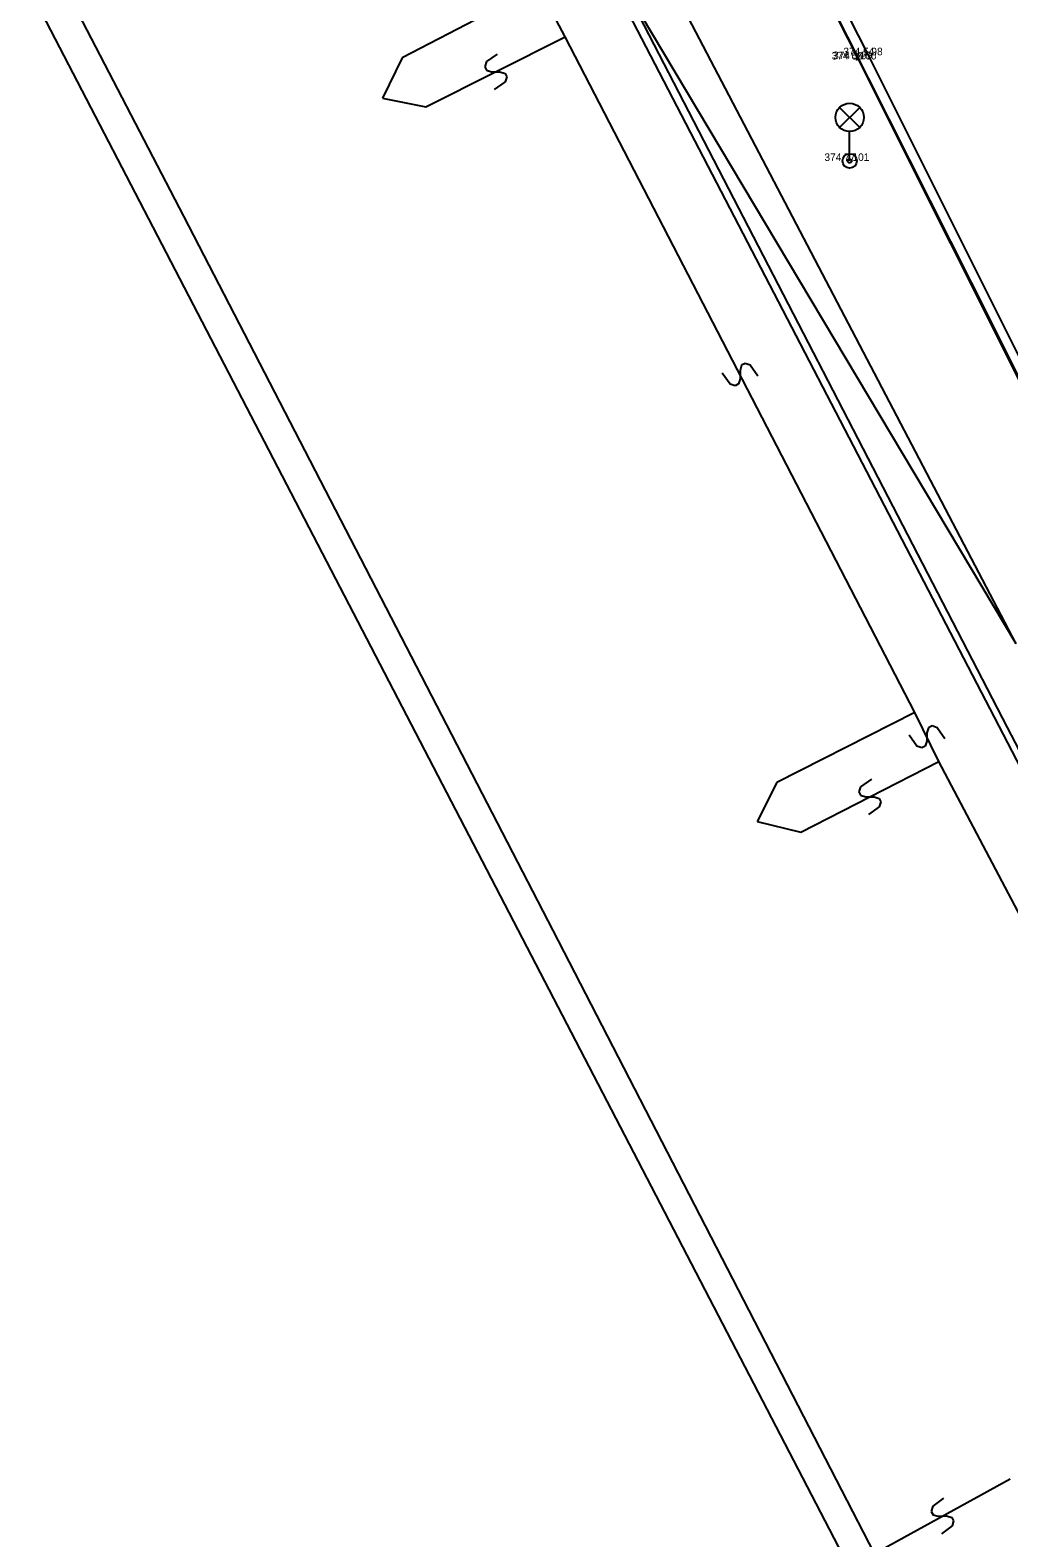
# Model space of a CAD drawing. Extents: x -601196 to -600262, y -1082523 to -1081922.
# Drawn here: x -600494.1 to -600468.24, y -1082356.61 to -1082316.78 of the extents above; entities that cross this region are included whole.
import ezdxf

# ---------------------------------------------------------------- set-up
doc = ezdxf.new("R2010")
doc.units = 0
for name, color, linetype in [('Vrstva 1', 7, 'Continuous'), ('Vrstva 10', 7, 'Continuous'), ('Vrstva 11', 7, 'Continuous'), ('Vrstva 2', 7, 'Continuous'), ('Vrstva 20', 7, 'Continuous'), ('Vrstva 3', 7, 'Continuous'), ('Vrstva 33', 7, 'Continuous'), ('Vrstva 47', 7, 'Continuous')]:
    doc.layers.add(name, color=color, linetype=linetype)

msp = doc.modelspace()

# ---------------------------------------------------------------- linework, layer by layer
at = {"layer": 'Vrstva 1'}
for p, q in [((-600471.95, -1082317.45), (-600471.95, -1082317.45)), ((-600472.26, -1082317.56), (-600472.26, -1082317.56)), ((-600472.22, -1082317.55), (-600472.22, -1082317.55)), ((-600472.45, -1082320.24), (-600472.45, -1082320.24))]:
    msp.add_line(p, q, dxfattribs=at)
at = {"layer": 'Vrstva 10'}
for p, q in [((-600472.22, -1082317.55), (-600475.82, -1082310.42)), ((-600461.09, -1082339.77), (-600472.22, -1082317.55))]:
    msp.add_line(p, q, dxfattribs=at)
at = {"layer": 'Vrstva 11'}
for p, q in [((-600471.95, -1082317.45), (-600475.59, -1082310.29)), ((-600460.84, -1082339.7), (-600471.95, -1082317.45))]:
    msp.add_line(p, q, dxfattribs=at)
at = {"layer": 'Vrstva 20'}
for p, q in [((-600472.27, -1082317.56), (-600472.25, -1082317.56)), ((-600472.26, -1082317.545), (-600472.26, -1082317.56)), ((-600472.26, -1082317.575), (-600472.26, -1082317.56))]:
    msp.add_line(p, q, dxfattribs=at)
at = {"layer": 'Vrstva 33'}
for p, q in [((-600472.715, -1082318.825), (-600472.185, -1082319.355)), ((-600472.715, -1082319.355), (-600472.185, -1082318.825)), ((-600472.45, -1082320.24), (-600472.45, -1082319.465))]:
    msp.add_line(p, q, dxfattribs=at)
for centre, radius in [((-600472.45, -1082319.09), 0.375), ((-600472.45, -1082320.24), 0.19), ((-600472.45, -1082320.24), 0.05)]:
    msp.add_circle(centre, radius, dxfattribs=at)
at = {"layer": 'Vrstva 47'}
for p, q in [((-600472.11, -1082358.06), (-600511.64, -1082281.96)), ((-600490.04, -1082321.7), (-600500.34, -1082301.83)), ((-600468.05, -1082332.99), (-600480.72, -1082308.79)), ((-600476.01, -1082310), (-600469.24, -1082323.45)), ((-600458.72, -1082354.01), (-600480.28, -1082312.49)), ((-600480.66, -1082315.64), (-600484.27, -1082317.52)), ((-600479.96, -1082316.96), (-600480.66, -1082315.64)), ((-600468.28, -1082335.2), (-600478.37, -1082315.69)), ((-600468.05, -1082332.99), (-600478.37, -1082315.69)), ((-600483.64, -1082318.81), (-600479.96, -1082316.96)), ((-600470.73, -1082334.81), (-600479.96, -1082316.96)), ((-600481.756, -1082317.415), (-600482.046, -1082317.617)), ((-600484.27, -1082317.52), (-600484.79, -1082318.58)), ((-600482.046, -1082317.617), (-600482.09, -1082317.751)), ((-600482.09, -1082317.751), (-600482.046, -1082317.84)), ((-600482.046, -1082317.84), (-600481.911, -1082317.885)), ((-600481.911, -1082317.885), (-600481.688, -1082317.884)), ((-600481.553, -1082318.152), (-600481.843, -1082318.354)), ((-600481.688, -1082317.884), (-600481.553, -1082317.929)), ((-600481.553, -1082317.929), (-600481.509, -1082318.018)), ((-600481.509, -1082318.018), (-600481.553, -1082318.152)), ((-600484.79, -1082318.58), (-600483.64, -1082318.81)), ((-600480.28, -1082340.57), (-600490.04, -1082321.7)), ((-600469.24, -1082323.45), (-600465.5, -1082330.94)), ((-600475.609, -1082326.134), (-600475.815, -1082325.846)), ((-600475.303, -1082325.638), (-600475.346, -1082325.773)), ((-600475.346, -1082325.773), (-600475.343, -1082325.996)), ((-600475.214, -1082325.592), (-600475.303, -1082325.638)), ((-600475.08, -1082325.635), (-600475.214, -1082325.592)), ((-600474.874, -1082325.923), (-600475.08, -1082325.635)), ((-600475.475, -1082326.177), (-600475.609, -1082326.134)), ((-600475.386, -1082326.131), (-600475.475, -1082326.177)), ((-600475.343, -1082325.996), (-600475.386, -1082326.131)), ((-600470.73, -1082334.81), (-600474.37, -1082336.66)), ((-600470.09, -1082336.1), (-600470.73, -1082334.81)), ((-600470.409, -1082335.343), (-600470.41, -1082335.566)), ((-600470.364, -1082335.209), (-600470.409, -1082335.343)), ((-600470.274, -1082335.164), (-600470.364, -1082335.209)), ((-600470.14, -1082335.209), (-600470.274, -1082335.164)), ((-600469.94, -1082335.501), (-600470.14, -1082335.209)), ((-600460.9, -1082349.46), (-600468.28, -1082335.2)), ((-600470.679, -1082335.7), (-600470.879, -1082335.408)), ((-600470.545, -1082335.745), (-600470.679, -1082335.7)), ((-600470.455, -1082335.7), (-600470.545, -1082335.745)), ((-600470.41, -1082335.566), (-600470.455, -1082335.7)), ((-600473.74, -1082337.97), (-600470.09, -1082336.1)), ((-600461.84, -1082351.78), (-600470.09, -1082336.1)), ((-600471.874, -1082336.565), (-600472.163, -1082336.769)), ((-600474.37, -1082336.66), (-600474.89, -1082337.69)), ((-600472.163, -1082336.769), (-600472.207, -1082336.903)), ((-600472.207, -1082336.903), (-600472.161, -1082336.992)), ((-600472.161, -1082336.992), (-600472.026, -1082337.036)), ((-600472.026, -1082337.036), (-600471.803, -1082337.033)), ((-600471.666, -1082337.3), (-600471.955, -1082337.505)), ((-600471.803, -1082337.033), (-600471.668, -1082337.077)), ((-600471.668, -1082337.077), (-600471.623, -1082337.166)), ((-600471.623, -1082337.166), (-600471.666, -1082337.3)), ((-600474.89, -1082337.69), (-600473.74, -1082337.97)), ((-600471.79, -1082357.02), (-600480.28, -1082340.57)), ((-600471.79, -1082357.02), (-600468.21, -1082355.05)), ((-600469.973, -1082355.564), (-600470.256, -1082355.776)), ((-600470.256, -1082355.776), (-600470.295, -1082355.912)), ((-600470.295, -1082355.912), (-600470.247, -1082356)), ((-600470.247, -1082356), (-600470.111, -1082356.039)), ((-600470.111, -1082356.039), (-600469.888, -1082356.03)), ((-600469.888, -1082356.03), (-600469.752, -1082356.07)), ((-600469.752, -1082356.07), (-600469.704, -1082356.157)), ((-600469.743, -1082356.293), (-600470.026, -1082356.505)), ((-600469.704, -1082356.157), (-600469.743, -1082356.293))]:
    msp.add_line(p, q, dxfattribs=at)

# ---------------------------------------------------------------- texts
at = {"layer": 'Vrstva 2'}
for s, p in [(' 100', (-600472.26, -1082317.56)), (' 99', (-600472.22, -1082317.55)), (' 98', (-600471.95, -1082317.45)), (' 101', (-600472.45, -1082320.24))]:
    msp.add_text(s, height=0.2, dxfattribs=at).set_placement(p)
at = {"layer": 'Vrstva 3'}
for s, p in [('374 66 ', (-600472.926, -1082317.56)), ('374 54 ', (-600472.886, -1082317.55)), ('374 54 ', (-600472.616, -1082317.45)), ('374 77 ', (-600473.116, -1082320.24))]:
    msp.add_text(s, height=0.2, dxfattribs=at).set_placement(p)

doc.saveas('drawing.dxf')
